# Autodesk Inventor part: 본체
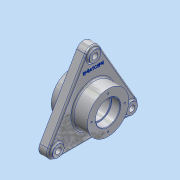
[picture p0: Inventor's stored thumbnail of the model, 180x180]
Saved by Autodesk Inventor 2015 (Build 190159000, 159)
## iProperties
Created: 2023-04
Part Number: 본체
Material: 알루미늄 6061
Document SubType Name: Modeling
Designer: SCD-A04
Density: 2.7 g/cm^3
Appearance: 알루미늄 - 평지
Mass: 1219.48 g
Surface Area: 639.911 cm^2
Volume: 451.66 cm^3
Author: SCD-A04
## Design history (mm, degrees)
sketch "스케치5"
  geometry: L1 (-13.856, 90)-(-84.87, -33); L2 (-71.014, -57)-(71.014, -57); L3 (84.87, -33)-(13.856, 90); A1 r 82 centre (0, 0) between (0, 82) and (71.014, -41); A2 r 16 centre (0, 82) between (13.856, 90) and (-13.856, 90); A3 r 16 centre (71.014, -41) between (71.014, -57) and (84.87, -33); A4 r 16 centre (-71.014, -41) between (-84.87, -33) and (-71.014, -57); 1 further point
  constraints: 9 point on circle, 6 end point, 6 tangent, 4 centre point, 2 equal length, 2 equal radius, 1 coincident, 1 horizontal
  dimensions: "d3" = 164 diameter of A1; "d4" = 16 radius of A2
extrude "돌출1" new body sketch "스케치5" stored distance "d5" = 18; taper "d6" = 0 deg
sketch "스케치7"
  geometry: C1 r 82 at (0, 0); C2 r 11 at (-82, 0); C3 r 11 at (41, -71.014); C4 r 11 at (41, 71.014); A1 r 16 centre (41, -71.014) between (33, -84.87) and (57, -71.014) reference; A2 r 16 centre (41, 71.014) between (57, 71.014) and (33, 84.87) reference; A3 r 16 centre (-82, 0) between (-90, 13.856) and (-90, -13.856) reference; 1 further point
  constraints: 4 centre point, 4 coincident
  dimensions: "d7" = 164 diameter of C1; "d10" = 22 diameter of C2; "d11" = 22 diameter of C3; "d12" = 22 diameter of C4
extrude "돌출2" join sketch "스케치7" distance "d13" = 4; taper "d14" = 0 deg
sketch "스케치8"
  geometry: C1 r 40 at (0, 0); 1 further point
  constraints: 1 centre point, 1 coincident
  dimensions: "d15" = 80 diameter of C1
extrude "돌출3" join sketch "스케치8" distance "d16" = 29; taper "d17" = 0 deg
sketch "스케치9"
  geometry: C1 r 40 at (0, 0); 1 further point
  constraints: 1 centre point, 1 coincident
  dimensions: "d18" = 80 diameter of C1
extrude "돌출4" join sketch "스케치9" distance "d19" = 23; taper "d20" = 0 deg
sketch "스케치10"
  geometry: C1 r 40 at (0, 0) reference; C2 r 45 at (0, 0)
  constraints: 1 centre point, 1 coincident
  dimensions: "d21" = 90 diameter of C2
extrude "돌출5" join sketch "스케치10" distance "d22" = 5; taper "d23" = 0 deg
hole "구멍1" diameter "d26" = 42; stored, may be unused: countersink angle "d30" = 90 deg, drill point angle "d32" = 0 deg; dims "d24" = 10, "d25" = 10, "d27" = 15.875, "d28" = 47, "d29" = 17, "d31" = 8
hole "구멍2" diameter "d35" = 42; stored, may be unused: countersink angle "d39" = 90 deg, drill point angle "d41" = 0 deg; dims "d33" = 10, "d34" = 10, "d36" = 15.875, "d37" = 47, "d38" = 17, "d40" = 8
sketch "스케치11"
  geometry: L1 (0, 0)-(-32, 0); C1 r 40 at (0, 0) reference
  constraints: 2 end point, 1 horizontal
  dimensions: "d43" = 32 distance of L1.start L1.end
hole "구멍3" sketch "스케치11" at (-32, 0) diameter "d44" = 3.242; stored, may be unused: countersink angle "d48" = 90 deg, drill point angle "d50" = 118 deg; dims "d45" = 8, "d46" = 19.05, "d47" = 4.775, "d49" = 10
sketch "스케치12"
  geometry: L1 (0, 0)-(32, 0); C1 r 40 at (0, 0) reference
  constraints: 2 end point, 1 horizontal
  dimensions: "d54" = 32 distance of L1.start L1.end
hole "구멍4" sketch "스케치12" at (32, 0) diameter "d55" = 3.242; stored, may be unused: countersink angle "d59" = 90 deg, drill point angle "d61" = 118 deg; dims "d56" = 8, "d57" = 19.05, "d58" = 4.775, "d60" = 10
sketch "스케치14"
  geometry: C1 r 11 at (0, 0) reference; C2 r 5.5 at (0, 0); 1 further point
  constraints: 1 centre point, 1 coincident
  dimensions: "d66" = 11 diameter of C2
hole "구멍5" sketch "스케치14" at (0, 0) diameter "d67" = 11; stored, may be unused: countersink angle "d71" = 90 deg, drill point angle "d73" = 118 deg; dims "d68" = 8, "d69" = 19.05, "d70" = 4.775, "d72" = 10
fillet "모깎기1" dims "d77" = 3
fillet "모깎기2" dims "d78" = 3
fillet "모깎기3" dims "d79" = 3
sketch "스케치15"
  geometry: C1 r 43 at (0, 0) reference; 1 further point
  constraints: 1 horizontal alignment, 1 other
  dimensions: "d80" = 60 distance of C1.centre point (-60, 0)
feature "엠보싱1" sketch "스케치15" dims "d3" = 164, "d4" = 16, "d12" = 22, "d81" = 0.5, "d82" = 0
chamfer "모따기1" distance "d83" = 1; stored, may be unused: second distance "d84" = 2, angle "d85" = 45 deg
fillet "모깎기4" dims "d86" = 0.6
node "솔리드1"
pattern_circular "원형 패턴1" dims angle "d52" = 360 deg
pattern_circular "원형 패턴2" dims angle "d63" = 360 deg
pattern_circular "원형 패턴3" dims angle "d75" = 360 deg
